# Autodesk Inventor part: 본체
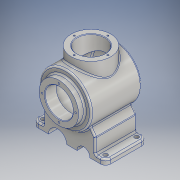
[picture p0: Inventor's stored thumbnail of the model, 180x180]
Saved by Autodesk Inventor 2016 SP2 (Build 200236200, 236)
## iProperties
Created: 2018-08
Part Number: 본체
Material: 알루미늄 6061
Document SubType Name: Modeling
Designer: Administrator
Density: 2.7 g/cm^3
Appearance: 알루미늄 - 평지
Mass: 1879.09 g
Surface Area: 1087.45 cm^2
Volume: 695.959 cm^3
Author: Administrator
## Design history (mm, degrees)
sketch "스케치1"
  geometry: L1 (12, 132)-(108.671, 132); L2 (120, 82)-(0, 82); L3 (0, 82)-(0, 120); L4 (12, 132)-(12, 120); L5 (12, 120)-(0, 120); L6 (102.163, 122)-(22, 122); L7 (22, 122)-(22, 109); L8 (0, 109)-(22, 109); L9 (0, 82)-(0, 109); A1 r 116 centre (4, 82) between (120, 82) and (108.671, 132); A2 r 106 centre (4, 82) between (110, 82) and (102.163, 122); 1 further point
  constraints: 18 end point, 4 point on circle, 4 point on line, 3 vertical, 2 centre point, 2 horizontal, 1 parallel
  dimensions: "d0" = 82 distance from line of point (0, 0) L2; "d2" = 12 distance of L4.end L3.end; "d4" = 76 diameter of L5 L2; "d5" = 100 diameter of L1 L2; "d6" = 116 radius of A1; "d7" = 120 distance from line of L3 L2.start; "d8" = 10 radial gap between concentric circles of A1 A2; "d9" = 22 distance of L8.start L7.end; "d10" = 54 diameter of L8 L2; "d11" = 10 distance between parallel lines of L1 L6; "d131" = 108 distance from line of L2.start L4 (derived)
revolve "회전1" stored, may be unused: angle "d12" = 90 deg
sketch "스케치2"
  geometry: L1 (0, 0)-(32, 0); L2 (0, -70)-(0, 0); L3 (10, -70)-(10, -50); L4 (10, -50)-(38.563, -50); L5 (10, -70)-(0, -70); L6 (38.563, -50)-(52.41, -40.304); L7 (0, 70)-(0, 0); L8 (10, 70)-(10, 50); L9 (10, 50)-(38.563, 50); L10 (10, 70)-(0, 70); L11 (38.563, 50)-(52.41, 40.304); A1 r 50 centre (82, 0) between (32, 0) and (52.41, -40.304) reference
  constraints: 22 end point, 5 symmetric about line, 2 horizontal, 2 point on circle, 1 perpendicular, 1 vertical
  dimensions: "d13" = 82 distance from line of L2 A1.centre; "d14" = 70 distance of L2.start L1.start; "d15" = 10 distance of L3.start L2.start; "d16" = 20 distance of L3.start L3.end; "d19" = 35 deg angle of L5 L6
node "작업 평면1"
sketch "스케치3"
  geometry: L1 (0, -82)-(-70, -82); L2 (-70, -82)-(-70, -72); L3 (-70, -72)-(-50, -72); L4 (-50, -72)-(-50, -43.437); L5 (0, -82)-(0, -50); L6 (-70, -72)-(-40.304, -29.59); L7 (0, -82)-(70, -82); L8 (70, -82)-(70, -72); L9 (70, -72)-(50, -72); L10 (50, -72)-(50, -43.437); L11 (70, -72)-(40.304, -29.59); A1 r 50 centre (0, 0) between (0, -50) and (-40.304, -29.59) reference
  constraints: 22 end point, 5 symmetric about line, 3 perpendicular, 2 point on circle, 2 point on line, 1 horizontal, 1 vertical
  dimensions: "d21" = 70 distance of L1.start L1.end; "d22" = 10 distance of L1.end L2.end; "d23" = 35 deg angle of L2 L6; "d24" = 20 distance of L2.end L3.end
extrude "돌출1" join sketch "스케치3" stored distance "d25" = 80; taper "d26" = 0 deg
revolve "회전2" stored, may be unused: angle "d27" = 90 deg
sketch "스케치4"
  geometry: L1 (-70, -82)-(70, -82) reference; C1 r 17.5 at (-22.5, -82); C2 r 12.5 at (27.5, -82); 1 further point
  constraints: 2 centre point, 2 point on line
  dimensions: "d28" = 35 diameter of C1; "d29" = 22.5 distance of point (0, -82) C1.centre; "d30" = 25 diameter of C2; "d31" = 27.5 distance of point (0, -82) C2.centre
extrude "돌출2" cut sketch "스케치4" distance "d32" = 140; taper "d33" = 0 deg
node "작업 평면2"
sketch "스케치6"
  geometry: L1 (-22, 5)-(112.534, 5); L2 (-22, -33)-(-22, 43) reference; C1 r 38 at (40, 5)
  constraints: 2 end point, 1 centre point, 1 horizontal, 1 point on line
  dimensions: "d35" = 76 diameter of C1; "d36" = 62 distance from line of L2 C1.centre
extrude "돌출3" join sketch "스케치6" stored distance "d37" = 140; taper "d38" = 0 deg; dims "d13" = 82, "d14" = 70, "d15" = 10, "d16" = 20, "d19" = 35 deg
hole "구멍1" diameter "d41" = 54; stored, may be unused: countersink angle "d45" = 90 deg, drill point angle "d47" = 118 deg; dims "d39" = 10, "d40" = 10, "d42" = 6, "d43" = 4, "d44" = 2, "d46" = 8
sketch "스케치7" dims "d48" = 65
  geometry: L1 (0, 0)-(0, 32.5); C1 r 38 at (0, 0) reference; C2 r 3.693 at (0, 32.5); C3 r 3.693 at (-32.5, 0); C4 r 3.693 at (0, -32.5); C5 r 3.693 at (32.5, 0); 1 further point
  constraints: 4 centre point, 2 coincident, 2 end point, 1 vertical, 1 vertical alignment, 11 other
  dimensions: "d51" = 360 deg dimension on C1.centre C2.centre (derived)
sketch "스케치8" dims "d53" = 65
  geometry: L1 (0, 0)-(0, 32.5); C1 r 38 at (0, 0) reference; C2 r 4.049 at (0, 32.5); C3 r 4.049 at (-32.5, 0); C4 r 4.049 at (0, -32.5); C5 r 4.049 at (32.5, 0); 1 further point
  constraints: 4 centre point, 2 coincident, 2 end point, 1 vertical, 1 vertical alignment, 11 other
  dimensions: "d56" = 360 deg dimension on C1.centre C2.centre (derived)
hole "구멍2" sketch "스케치8" at (-32.5, 0), (0, 32.5), (32.5, 0), (0, -32.5) diameter "d58" = 3.242; stored, may be unused: countersink angle "d62" = 90 deg, drill point angle "d64" = 118 deg; dims "d59" = 8, "d60" = 4, "d61" = 2, "d63" = 10
hole "구멍3" sketch "스케치7" diameter "d65" = 3.242; stored, may be unused: countersink angle "d69" = 90 deg, drill point angle "d71" = 118 deg; dims "d66" = 8, "d67" = 4, "d68" = 2, "d70" = 10
fillet "모깎기1" dims "d72" = 3
fillet "모깎기2" dims "d73" = 3
fillet "모깎기3" dims "d74" = 10
hole "구멍4" diameter "d77" = 8; stored, may be unused: countersink angle "d81" = 90 deg, drill point angle "d83" = 0 deg; dims "d75" = 10, "d76" = 10, "d78" = 8, "d79" = 4, "d80" = 2, "d82" = 10
hole "구멍5" diameter "d86" = 8; stored, may be unused: countersink angle "d90" = 90 deg, drill point angle "d92" = 0 deg; dims "d84" = 10, "d85" = 10, "d87" = 8, "d88" = 4, "d89" = 2, "d91" = 10
hole "구멍6" diameter "d95" = 8; stored, may be unused: countersink angle "d99" = 90 deg, drill point angle "d101" = 0 deg; dims "d93" = 10, "d94" = 10, "d96" = 8, "d97" = 4, "d98" = 2, "d100" = 10
hole "구멍7" diameter "d104" = 8; stored, may be unused: countersink angle "d108" = 90 deg, drill point angle "d110" = 0 deg; dims "d102" = 10, "d103" = 10, "d105" = 8, "d106" = 4, "d107" = 2, "d109" = 10
fillet "모깎기4" dims "d111" = 3
fillet "모깎기5" dims "d112" = 3
fillet "모깎기6" dims "d113" = 3
fillet "모깎기7" dims "d114" = 3
fillet "모깎기8" dims "d115" = 3
chamfer "모따기1" distance "d116" = 1; stored, may be unused: second distance "d117" = 2, angle "d118" = 45 deg
chamfer "모따기2" distance "d119" = 1; stored, may be unused: second distance "d120" = 2, angle "d121" = 45 deg
node "작업 평면3"
sketch "스케치9"
  geometry: L1 (0, 0)-(0, -66.979); L2 (0, 0)-(0, 47.875); L3 (0, 0)-(32.5, 0); C1 r 50 at (0, 0) reference; A1 r 32.5 centre (0, 0) between (0, -32.5) and (32.5, 0); 1 further point
  constraints: 6 end point, 2 point on circle, 2 vertical, 1 centre point, 1 coincident, 1 point on line, 1 other
  dimensions: "d122" = 65 diameter of A1
feature "엠보싱1" sketch "스케치9" dims "d13" = 82, "d14" = 70, "d15" = 10, "d16" = 20, "d19" = 35 deg, "d123" = 0.5, "d124" = 0
node "직접 편집1"
node "직접 편집2"
node "직접 편집3"
node "직접 편집4"
node "솔리드1"
mirror "대칭1"
node "투영된 루프1"
feature "이동1" dims "d127" = 2
feature "이동2" dims "d130" = -2
feature "이동3" dims "d132" = -2
feature "이동4" dims "d135" = -2
feature "이동5" dims "d138" = -2
feature "이동6" dims "d141" = -2
other parameters: "d20" = -62, "d34" = -147, "d125" = 0, "d126" = 0, "d128" = 0, "d129" = 0, "d133" = 0, "d134" = 0, "d136" = 0, "d137" = 0, "d139" = 0, "d140" = 0, "d142" = 0, "d143" = 0
